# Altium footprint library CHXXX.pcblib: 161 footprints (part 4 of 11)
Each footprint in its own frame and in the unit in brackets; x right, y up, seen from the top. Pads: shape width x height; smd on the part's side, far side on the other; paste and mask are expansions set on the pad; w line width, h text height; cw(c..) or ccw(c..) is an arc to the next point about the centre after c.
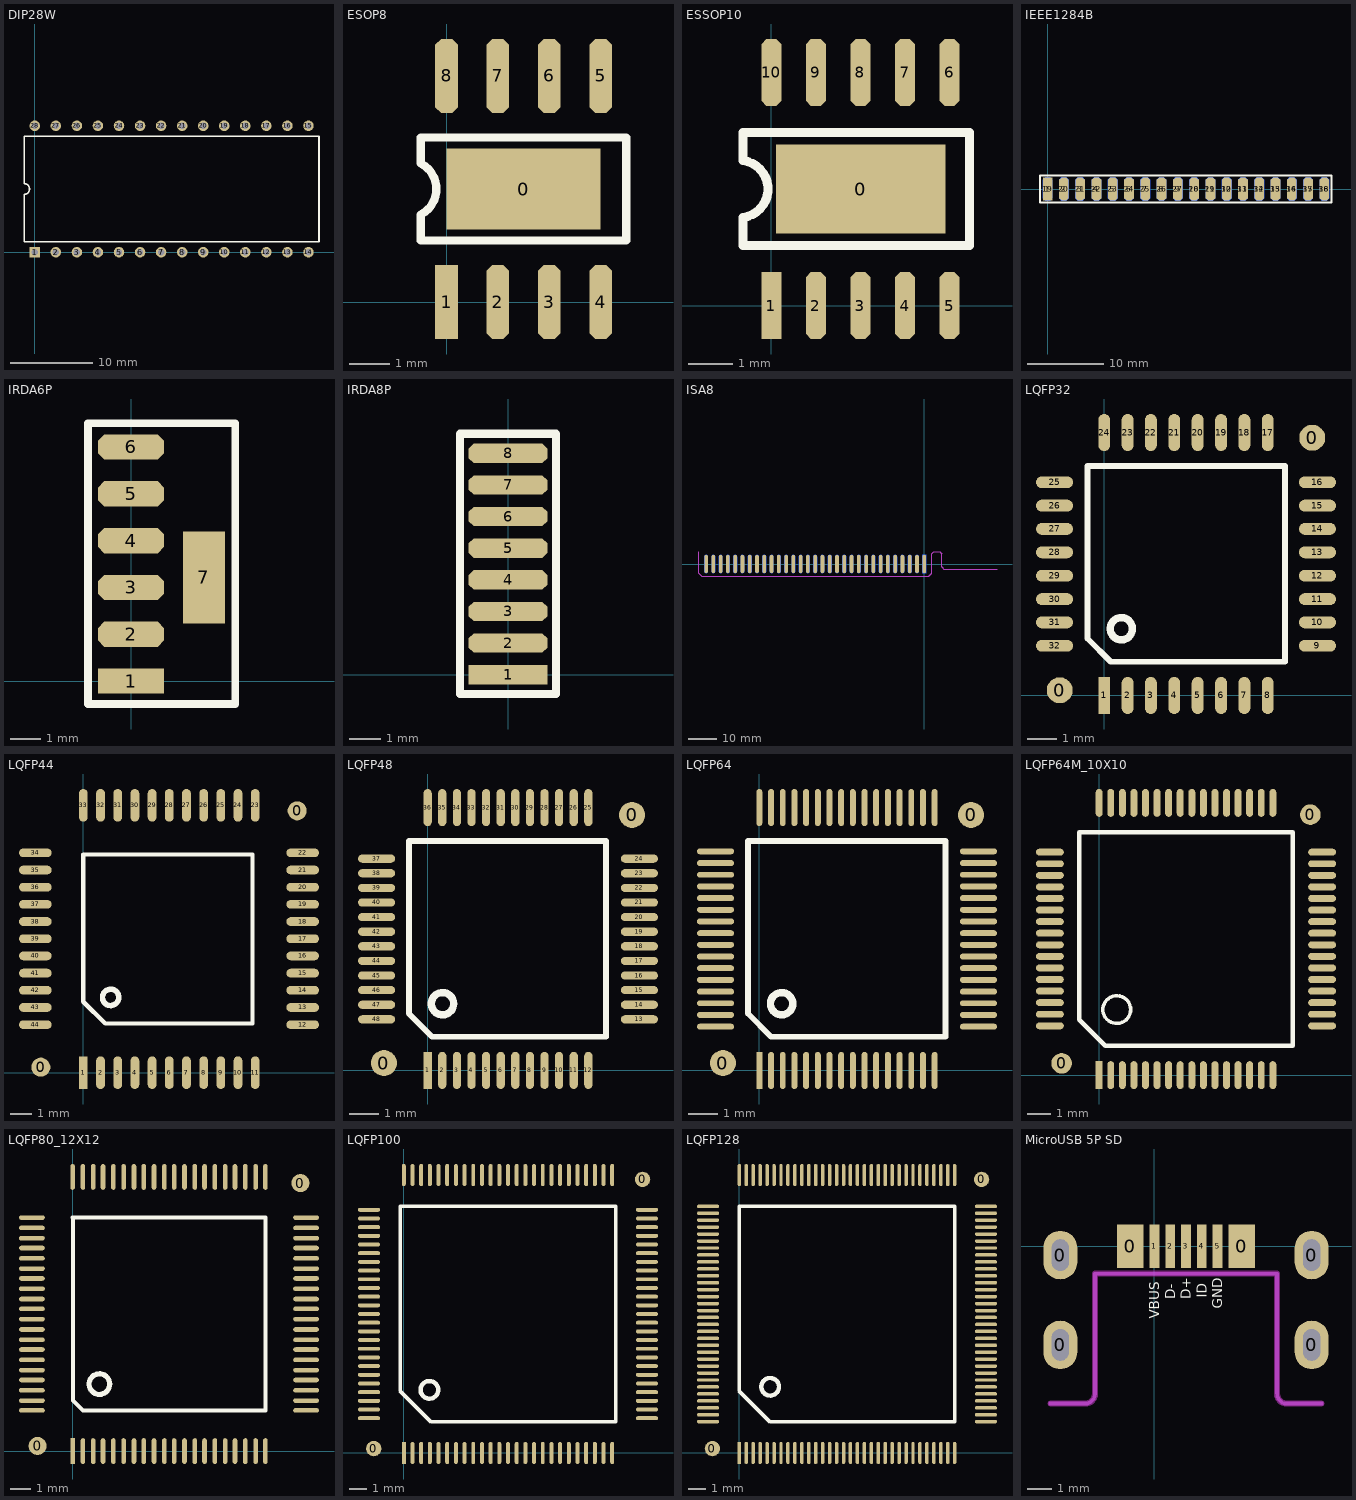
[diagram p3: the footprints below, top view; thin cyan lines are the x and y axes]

## DIP28W [mil]
pads (28):
  rect 50x50 hole 30: 1(0,0)
  round 50 hole 30: 2(100,0) 3(200,0) 4(300,0) 5(400,0) 6(500,0) 7(600,0) 8(700,0) 9(800,0) 10(900,0) 11(1000,0) 12(1100,0) 13(1200,0) 14(1300,0) 15(1300,600) 16(1200,600) 17(1100,600) 18(1000,600) 19(900,600) 20(800,600) 21(700,600) 22(600,600) 23(500,600) 24(400,600) 25(300,600) 26(200,600) 27(100,600) 28(0,600)
TopOverlay:
  lines w8: -50,50 1350,50 1350,550 -50,550 -50,325 cw(c-50,300) -50,275 -50,50

## ESOP8 [mil]
pads (9):
  rect 149.61x78.74 smd: 0(75,110)
  rect 22x72 smd: 1(0,0)
  oct 22x72 smd: 2(50,0) 3(100,0) 4(150,0) 5(150,220) 6(100,220) 7(50,220) 8(0,220)
TopOverlay:
  lines w8: -25,60 175,60 175,160 -25,160 -25,135 cw(c-38.11,110) -25,85 -25,60

## ESSOP10 [mm]
pads (11):
  rect 3.8x2 smd: 0(2.007,2.616)
  rect 0.45x1.5 smd: 1(0,0)
  oct 0.45x1.5 smd: 2(1,0) 3(2,0) 4(3,0) 5(4,0) 6(4,5.232) 7(3,5.232) 8(2,5.232) 9(1,5.232) 10(0,5.232)
TopOverlay:
  lines w0.203: -0.635,1.346 4.445,1.346 4.445,3.886 -0.635,3.886 -0.635,3.251 cw(c-0.714,2.616) -0.635,1.981 -0.635,1.346

## IEEE1284B [mil]
pads (36):
  rect 50x120 smd: 1(0,0)
  oct 50x120 smd: 2(84.25,0) 3(168.5,0) 4(252.76,0) 5(337.01,0) 6(421.26,0) 7(505.51,0) 8(589.76,0) 9(674.02,0) 10(758.27,0) 11(842.52,0) 12(926.77,0) 13(1011.02,0) 14(1095.28,0) 15(1179.53,0) 16(1263.78,0) 17(1348.03,0) 18(1432.28,0)
  oct 50x120 smd far side: 19(0,0) 20(84.25,0) 21(168.5,0) 22(252.76,0) 23(337.01,0) 24(421.26,0) 25(505.51,0) 26(589.76,0) 27(674.02,0) 28(758.27,0) 29(842.52,0) 30(926.77,0) 31(1011.02,0) 32(1095.28,0) 33(1179.53,0) 34(1263.78,0) 35(1348.03,0) 36(1432.28,0)
TopOverlay:
  lines w10: -40,-70 -40,70 1470,70 1470,-70 -40,-70

## IRDA6P [mil]
pads (7):
  rect 86x33 smd: 1(0,0)
  oct 86x33 smd: 2(0,60.91) 3(0,121.93) 4(0,182.95) 5(0,243.98) 6(0,305)
  rect 55x120 smd: 7(95,135)
TopOverlay:
  lines w10: -56,-30 -56,336 136,336 136,-30 -56,-30

## IRDA8P [mil]
pads (8):
  rect 98x24 smd: 1(0,0)
  oct 98x24 smd: 2(0,39.37) 3(0,78.74) 4(0,118.11) 5(0,157.48) 6(0,196.85) 7(0,236.22) 8(0,275.59)
TopOverlay:
  lines w10: -60,-24 -60,300 60,300 60,-24 -60,-24

## ISA8 [mm]
pads (62):
  rect 1.27x6.35 smd far side: 1(0,0)
  oval 1.27x6.35 smd far side: 2(-2.54,0) 3(-5.08,0) 4(-7.62,0) 5(-10.16,0) 6(-12.7,0) 7(-15.24,0) 8(-17.78,0) 9(-20.32,0) 10(-22.86,0) 11(-25.4,0) 12(-27.94,0) 13(-30.48,0) 14(-33.02,0) 15(-35.56,0) 16(-38.1,0) 17(-40.64,0) 18(-43.18,0) 19(-45.72,0) 20(-48.26,0) 21(-50.8,0) 22(-53.34,0) 23(-55.88,0) 24(-58.42,0) 25(-60.96,0) 26(-63.5,0) 27(-66.04,0) 28(-68.58,0) 29(-71.12,0) 30(-73.66,0) 31(-76.2,0)
  oval 1.27x6.35 smd: 32(-76.2,0) 33(-73.66,0) 34(-71.12,0) 35(-68.58,0) 36(-66.04,0) 37(-63.5,0) 38(-60.96,0) 39(-58.42,0) 40(-55.88,0) 41(-53.34,0) 42(-50.8,0) 43(-48.26,0) 44(-45.72,0) 45(-43.18,0) 46(-40.64,0) 47(-38.1,0) 48(-35.56,0) 49(-33.02,0) 50(-30.48,0) 51(-27.94,0) 52(-25.4,0) 53(-22.86,0) 54(-20.32,0) 55(-17.78,0) 56(-15.24,0) 57(-12.7,0) 58(-10.16,0) 59(-7.62,0) 60(-5.08,0) 61(-2.54,0) 62(0,0)
TopSolder:
  rectangle: -78.74,-4.318 2.54,3.302
BottomSolder:
  rectangle: -78.74,-4.318 2.54,3.302
KeepOutLayer:
  lines w0.254: -78.74,4.318 -78.74,-3.302 -77.724,-4.318 1.524,-4.318 2.54,-3.302 2.54,3.556 3.302,4.318 5.334,4.318 6.096,3.556 6.096,-1.016 6.858,-1.778 25.4,-1.778
Mechanical1:
  lines w0.254: -78.74,4.318 -78.74,-3.302 -77.724,-4.318 1.524,-4.318 2.54,-3.302 2.54,3.556 3.302,4.318 5.334,4.318 6.096,3.556 6.096,-1.016 6.858,-1.778 25.4,-1.778

## LQFP32 [mil]
pads (34):
  round 35 smd: 0(-60,7) 0(280.47,347.47)
  rect 16x50 smd: 1(0,0)
  oval 16x50 smd: 2(31.5,0) 3(62.99,0) 4(94.49,0) 5(125.98,0) 6(157.48,0) 7(188.98,0) 8(220.47,0) 17(220.47,354.5) 18(188.98,354.5) 19(157.48,354.5) 20(125.98,354.5) 21(94.49,354.5) 22(62.99,354.5) 23(31.5,354.5) 24(0,354.5)
  oval 50x16 smd: 9(287.5,67) 10(287.5,98.5) 11(287.5,129.99) 12(287.5,161.49) 13(287.5,192.98) 14(287.5,224.48) 15(287.5,255.98) 16(287.5,287.47) 25(-67,287.47) 26(-67,255.98) 27(-67,224.48) 28(-67,192.98) 29(-67,161.49) 30(-67,129.99) 31(-67,98.5) 32(-67,67)
TopOverlay:
  circle w10: c23,90 r15
  lines w7.87: -22.42,76.66 8.83,45.42
  lines w8: -22.42,76.66 -22.42,309.42 243.58,309.42 243.58,45.42 8.83,45.42

## LQFP44 [mil]
pads (46):
  round 35 smd: 0(-78,10) 0(392,480)
  rect 16x60 smd: 1(0,0)
  oval 16x60 smd: 2(31.5,0) 3(63,0) 4(94.49,0) 5(126,0) 6(157.48,0) 7(188.98,0) 8(220.47,0) 9(251.97,0) 10(283.46,0) 11(314.96,0) 23(314.96,490) 24(283.46,490) 25(251.97,490) 26(220.47,490) 27(188.98,490) 28(157.48,490) 29(126,490) 30(94.49,490) 31(63,490) 32(31.5,490) 33(0,490)
  oval 60x16 smd: 12(402,88) 13(402,119.49) 14(402,151) 15(402,182.48) 16(402,214) 17(402,245.47) 18(402,276.97) 19(402,308.46) 20(402,339.96) 21(402,371.46) 22(402,402.95) 34(-88,402.95) 35(-88,371.46) 36(-88,339.96) 37(-88,308.46) 38(-88,276.97) 39(-88,245.47) 40(-88,214) 41(-88,182.48) 42(-88,151) 43(-88,119.49) 44(-88,88)
TopOverlay:
  circle w10: c50,138 r15
  lines w8: 0,130 40,90 310,90 310,400 0,400 0,130

## LQFP48 [mm]
pads (50):
  round 0.889 smd: 0(-1.496,0.254) 0(6.996,8.746)
  rect 0.28x1.27 smd mask+0.051: 1(0,0)
  oval 0.28x1.27 smd mask+0.051: 2(0.5,0) 3(1,0) 4(1.5,0) 5(2,0) 6(2.5,0) 7(3,0) 8(3.5,0) 9(4,0) 10(4.5,0) 11(5,0) 12(5.5,0) 25(5.5,9) 26(5,9) 27(4.5,9) 28(4,9) 29(3.5,9) 30(3,9) 31(2.5,9) 32(2,9) 33(1.5,9) 34(1,9) 35(0.5,9) 36(0,9)
  oval 1.27x0.28 smd mask+0.051: 13(7.25,1.75) 14(7.25,2.25) 15(7.25,2.75) 16(7.25,3.25) 17(7.25,3.75) 18(7.25,4.25) 19(7.25,4.75) 20(7.25,5.25) 21(7.25,5.75) 22(7.25,6.25) 23(7.25,6.75) 24(7.25,7.25) 37(-1.75,7.25) 38(-1.75,6.75) 39(-1.75,6.25) 40(-1.75,5.75) 41(-1.75,5.25) 42(-1.75,4.75) 43(-1.75,4.25) 44(-1.75,3.75) 45(-1.75,3.25) 46(-1.75,2.75) 47(-1.75,2.25) 48(-1.75,1.75)
TopOverlay:
  circle w0.254: c0.508,2.286 r0.381
  lines w0.2: -0.646,1.947 0.148,1.154
  lines w0.203: -0.646,1.947 -0.646,7.859 6.111,7.859 6.111,1.154 0.148,1.154

## LQFP64 [mm]
pads (66):
  round 0.889 smd: 0(-1.246,0.254) 0(7.246,8.746)
  rect 0.203x1.27 smd mask+0.051: 1(0,0)
  oval 0.203x1.27 smd mask+0.051: 2(0.4,0) 3(0.8,0) 4(1.2,0) 5(1.6,0) 6(2,0) 7(2.4,0) 8(2.8,0) 9(3.2,0) 10(3.6,0) 11(4,0) 12(4.4,0) 13(4.8,0) 14(5.2,0) 15(5.6,0) 16(6,0) 33(6,9) 34(5.6,9) 35(5.2,9) 36(4.8,9) 37(4.4,9) 38(4,9) 39(3.6,9) 40(3.2,9) 41(2.8,9) 42(2.4,9) 43(2,9) 44(1.6,9) 45(1.2,9) 46(0.8,9) 47(0.4,9) 48(0,9)
  oval 1.27x0.203 smd mask+0.051: 17(7.5,1.5) 18(7.5,1.9) 19(7.5,2.3) 20(7.5,2.7) 21(7.5,3.1) 22(7.5,3.5) 23(7.5,3.9) 24(7.5,4.3) 25(7.5,4.7) 26(7.5,5.1) 27(7.5,5.5) 28(7.5,5.9) 29(7.5,6.3) 30(7.5,6.7) 31(7.5,7.1) 32(7.5,7.5) 49(-1.5,7.5) 50(-1.5,7.1) 51(-1.5,6.7) 52(-1.5,6.3) 53(-1.5,5.9) 54(-1.5,5.5) 55(-1.5,5.1) 56(-1.5,4.7) 57(-1.5,4.3) 58(-1.5,3.9) 59(-1.5,3.5) 60(-1.5,3.1) 61(-1.5,2.7) 62(-1.5,2.3) 63(-1.5,1.9) 64(-1.5,1.5)
TopOverlay:
  circle w0.254: c0.762,2.286 r0.381
  lines w0.2: -0.392,1.947 0.402,1.154
  lines w0.203: -0.392,1.947 -0.392,7.859 6.365,7.859 6.365,1.154 0.402,1.154

## LQFP64M_10X10 [mm]
pads (66):
  round 0.889 smd: 0(-1.619,0.508) 0(9.119,11.246)
  rect 0.3x1.2 smd mask+0.051: 1(0,0)
  oval 0.3x1.2 smd mask+0.051: 2(0.5,0) 3(1,0) 4(1.5,0) 5(2,0) 6(2.5,0) 7(3,0) 8(3.5,0) 9(4,0) 10(4.5,0) 11(5,0) 12(5.5,0) 13(6,0) 14(6.5,0) 15(7,0) 16(7.5,0) 33(7.5,11.754) 34(7,11.754) 35(6.5,11.754) 36(6,11.754) 37(5.5,11.754) 38(5,11.754) 39(4.5,11.754) 40(4,11.754) 41(3.5,11.754) 42(3,11.754) 43(2.5,11.754) 44(2,11.754) 45(1.5,11.754) 46(1,11.754) 47(0.5,11.754) 48(0,11.754)
  oval 1.2x0.3 smd mask+0.051: 17(9.627,2.127) 18(9.627,2.627) 19(9.627,3.127) 20(9.627,3.627) 21(9.627,4.127) 22(9.627,4.627) 23(9.627,5.127) 24(9.627,5.627) 25(9.627,6.127) 26(9.627,6.627) 27(9.627,7.127) 28(9.627,7.627) 29(9.627,8.127) 30(9.627,8.627) 31(9.627,9.127) 32(9.627,9.627) 49(-2.127,9.627) 50(-2.127,9.127) 51(-2.127,8.627) 52(-2.127,8.127) 53(-2.127,7.627) 54(-2.127,7.127) 55(-2.127,6.627) 56(-2.127,6.127) 57(-2.127,5.627) 58(-2.127,5.127) 59(-2.127,4.627) 60(-2.127,4.127) 61(-2.127,3.627) 62(-2.127,3.127) 63(-2.127,2.627) 64(-2.127,2.127)
TopOverlay:
  circle w0.152: c0.762,2.829 r0.6
  lines w0.2: -0.865,2.397 -0.865,10.492 8.365,10.492 8.365,1.262 0.27,1.262 -0.865,2.397

## LQFP80_12X12 [mil]
pads (82):
  round 35 smd: 0(-68,10) 0(442,520)
  rect 9x50 smd mask+2: 1(0,0)
  oval 9x50 smd mask+2: 2(20,0) 3(40,0) 4(59,0) 5(79,0) 6(99,0) 7(119,0) 8(138,0) 9(158,0) 10(178,0) 11(197,0) 12(217,0) 13(237,0) 14(256,0) 15(276,0) 16(296,0) 17(315,0) 18(335,0) 19(355,0) 20(374,0) 41(374,532) 42(355,532) 43(335,532) 44(315,532) 45(296,532) 46(276,532) 47(256,532) 48(237,532) 49(217,532) 50(197,532) 51(178,532) 52(158,532) 53(138,532) 54(119,532) 55(99,532) 56(79,532) 57(59,532) 58(40,532) 59(20,532) 60(0,532)
  oval 50x9 smd mask+2: 21(453,79) 22(453,98) 23(453,118) 24(453,138) 25(453,157) 26(453,177) 27(453,197) 28(453,216) 29(453,236) 30(453,256) 31(453,276) 32(453,295) 33(453,315) 34(453,335) 35(453,354) 36(453,374) 37(453,394) 38(453,413) 39(453,433) 40(453,453) 61(-79,453) 62(-79,433) 63(-79,413) 64(-79,394) 65(-79,374) 66(-79,354) 67(-79,335) 68(-79,315) 69(-79,295) 70(-79,276) 71(-79,256) 72(-79,236) 73(-79,216) 74(-79,197) 75(-79,177) 76(-79,157) 77(-79,138) 78(-79,118) 79(-79,98) 80(-79,79)
TopOverlay:
  circle w10: c52,130 r20
  lines w8: 0,453 374,453 374,79 20,79 1,98 1,453

## LQFP100 [mm]
pads (102):
  round 0.889 smd: 0(-1.727,0.254) 0(13.746,15.748)
  rect 0.229x1.27 smd mask+0.051: 1(0,0)
  oval 0.229x1.27 smd mask+0.051: 2(0.5,0) 3(1,0) 4(1.5,0) 5(2,0) 6(2.5,0) 7(3,0) 8(3.5,0) 9(4,0) 10(4.5,0) 11(5,0) 12(5.5,0) 13(6,0) 14(6.5,0) 15(7,0) 16(7.5,0) 17(8,0) 18(8.5,0) 19(9,0) 20(9.5,0) 21(10,0) 22(10.5,0) 23(11,0) 24(11.5,0) 25(12,0) 51(12,16) 52(11.5,16) 53(11,16) 54(10.5,16) 55(10,16) 56(9.5,16) 57(9,16) 58(8.5,16) 59(8,16) 60(7.5,16) 61(7,16) 62(6.5,16) 63(6,16) 64(5.5,16) 65(5,16) 66(4.5,16) 67(4,16) 68(3.5,16) 69(3,16) 70(2.5,16) 71(2,16) 72(1.5,16) 73(1,16) 74(0.5,16) 75(0,16)
  oval 1.27x0.229 smd mask+0.051: 26(14,2) 27(14,2.5) 28(14,3) 29(14,3.5) 30(14,4) 31(14,4.5) 32(14,5) 33(14,5.5) 34(14,6) 35(14,6.5) 36(14,7) 37(14,7.5) 38(14,8) 39(14,8.5) 40(14,9) 41(14,9.5) 42(14,10) 43(14,10.5) 44(14,11) 45(14,11.5) 46(14,12) 47(14,12.5) 48(14,13) 49(14,13.5) 50(14,14) 76(-2,14) 77(-2,13.5) 78(-2,13) 79(-2,12.5) 80(-2,12) 81(-2,11.5) 82(-2,11) 83(-2,10.5) 84(-2,10) 85(-2,9.5) 86(-2,9) 87(-2,8.5) 88(-2,8) 89(-2,7.5) 90(-2,7) 91(-2,6.5) 92(-2,6) 93(-2,5.5) 94(-2,5) 95(-2,4.5) 96(-2,4) 97(-2,3.5) 98(-2,3) 99(-2,2.5) 100(-2,2)
TopOverlay:
  circle w0.254: c1.473,3.632 r0.508
  lines w0.2: -0.215,3.57 -0.215,14.215 12.215,14.215 12.215,1.785 1.57,1.785 -0.215,3.57

## LQFP128 [mm]
pads (130):
  round 0.889 smd: 0(-1.546,0.254) 0(13.946,15.746)
  rect 0.2x1.27 smd mask+0.051: 1(0,0)
  oval 0.2x1.27 smd mask+0.051: 2(0.4,0) 3(0.8,0) 4(1.2,0) 5(1.6,0) 6(2,0) 7(2.4,0) 8(2.8,0) 9(3.2,0) 10(3.6,0) 11(4,0) 12(4.4,0) 13(4.8,0) 14(5.2,0) 15(5.6,0) 16(6,0) 17(6.4,0) 18(6.8,0) 19(7.2,0) 20(7.6,0) 21(8,0) 22(8.4,0) 23(8.8,0) 24(9.2,0) 25(9.6,0) 26(10,0) 27(10.4,0) 28(10.8,0) 29(11.2,0) 30(11.6,0) 31(12,0) 32(12.4,0) 65(12.4,16) 66(12,16) 67(11.6,16) 68(11.2,16) 69(10.8,16) 70(10.4,16) 71(10,16) 72(9.6,16) 73(9.2,16) 74(8.8,16) 75(8.4,16) 76(8,16) 77(7.6,16) 78(7.2,16) 79(6.8,16) 80(6.4,16) 81(6,16) 82(5.6,16) 83(5.2,16) 84(4.8,16) 85(4.4,16) 86(4,16) 87(3.6,16) 88(3.2,16) 89(2.8,16) 90(2.4,16) 91(2,16) 92(1.6,16) 93(1.2,16) 94(0.8,16) 95(0.4,16) 96(0,16)
  oval 1.27x0.2 smd mask+0.051: 33(14.2,1.8) 34(14.2,2.2) 35(14.2,2.6) 36(14.2,3) 37(14.2,3.4) 38(14.2,3.8) 39(14.2,4.2) 40(14.2,4.6) 41(14.2,5) 42(14.2,5.4) 43(14.2,5.8) 44(14.2,6.2) 45(14.2,6.6) 46(14.2,7) 47(14.2,7.4) 48(14.2,7.8) 49(14.2,8.2) 50(14.2,8.6) 51(14.2,9) 52(14.2,9.4) 53(14.2,9.8) 54(14.2,10.2) 55(14.2,10.6) 56(14.2,11) 57(14.2,11.4) 58(14.2,11.8) 59(14.2,12.2) 60(14.2,12.6) 61(14.2,13) 62(14.2,13.4) 63(14.2,13.8) 64(14.2,14.2) 97(-1.8,14.2) 98(-1.8,13.8) 99(-1.8,13.4) 100(-1.8,13) 101(-1.8,12.6) 102(-1.8,12.2) 103(-1.8,11.8) 104(-1.8,11.4) 105(-1.8,11) 106(-1.8,10.6) 107(-1.8,10.2) 108(-1.8,9.8) 109(-1.8,9.4) 110(-1.8,9) 111(-1.8,8.6) 112(-1.8,8.2) 113(-1.8,7.8) 114(-1.8,7.4) 115(-1.8,7) 116(-1.8,6.6) 117(-1.8,6.2) 118(-1.8,5.8) 119(-1.8,5.4) 120(-1.8,5) 121(-1.8,4.6) 122(-1.8,4.2) 123(-1.8,3.8) 124(-1.8,3.4) 125(-1.8,3) 126(-1.8,2.6) 127(-1.8,2.2) 128(-1.8,1.8)
TopOverlay:
  circle w0.254: c1.778,3.81 r0.508
  lines w0.2: -0.015,3.57 -0.015,14.215 12.415,14.215 12.415,1.785 1.77,1.785 -0.015,3.57

## MicroUSB 5P SD [mm]
pads (11):
  oval 1.4x2 hole 0.7 slot 1.3 at 90 deg: 0(-3.875,-4.062) 0(-3.875,-0.362) 0(6.475,-4.062) 0(6.475,-0.362)
  rect 1.1x1.8 smd mask+0.051: 0(-1,0) 0(3.6,0)
  rect 0.4x1.8 smd mask+0.051: 1(0,0) 2(0.65,0) 3(1.3,0) 4(1.95,0) 5(2.6,0)
TopOverlay:
  text "GND" at 2.8,-2.577 h0.4
  text "ID" at 2.15,-2.11 h0.4
  text "D+" at 1.5,-2.177 h0.4
  text "D-" at 0.85,-2.177 h0.4
  text "VBUS" at 0.2,-2.977 h0.4
KeepOutLayer:
  lines w0.254: -4.277,-6.476 -2.85,-6.476 ccw(c-2.85,-6.076) -2.45,-6.076 -2.45,-1.126 5.05,-1.126 5.05,-6.076 ccw(c5.45,-6.076) 5.45,-6.476 6.877,-6.476
Mechanical1:
  lines w0.152: -4.277,-6.476 -2.85,-6.476 ccw(c-2.85,-6.076) -2.45,-6.076 -2.45,-1.126 5.05,-1.126 ; 6.877,-6.476 5.45,-6.476 cw(c5.45,-6.076) 5.05,-6.076 5.05,-1.126 ; 5.05,-1.126 5.05,-1.126
3D body "476420001.stp": height 1.78, standoff -1.2, extent -3.8,-6.597 6.4,0.633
